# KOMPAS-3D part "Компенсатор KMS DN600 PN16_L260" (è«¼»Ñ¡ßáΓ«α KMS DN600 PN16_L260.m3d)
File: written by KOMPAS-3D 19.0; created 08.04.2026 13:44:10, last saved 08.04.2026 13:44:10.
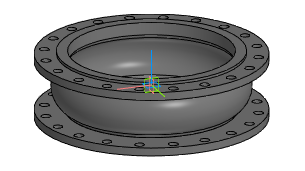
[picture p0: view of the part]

Document properties: Автор: Энергия; Полное имя файла: Z:\3.Личные\kachalov\3d для проектировщиков\7.1 Компенсатор\stp_Компенсатор KSM\Компенсатор KMS DN600 PN16_L260.m3d

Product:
- Part/product: Компенсатор KMS DN600 PN16_L260

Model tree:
1. Операция без истории:1  (labels: Компенсатор KMS DN600 PN16_L260)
